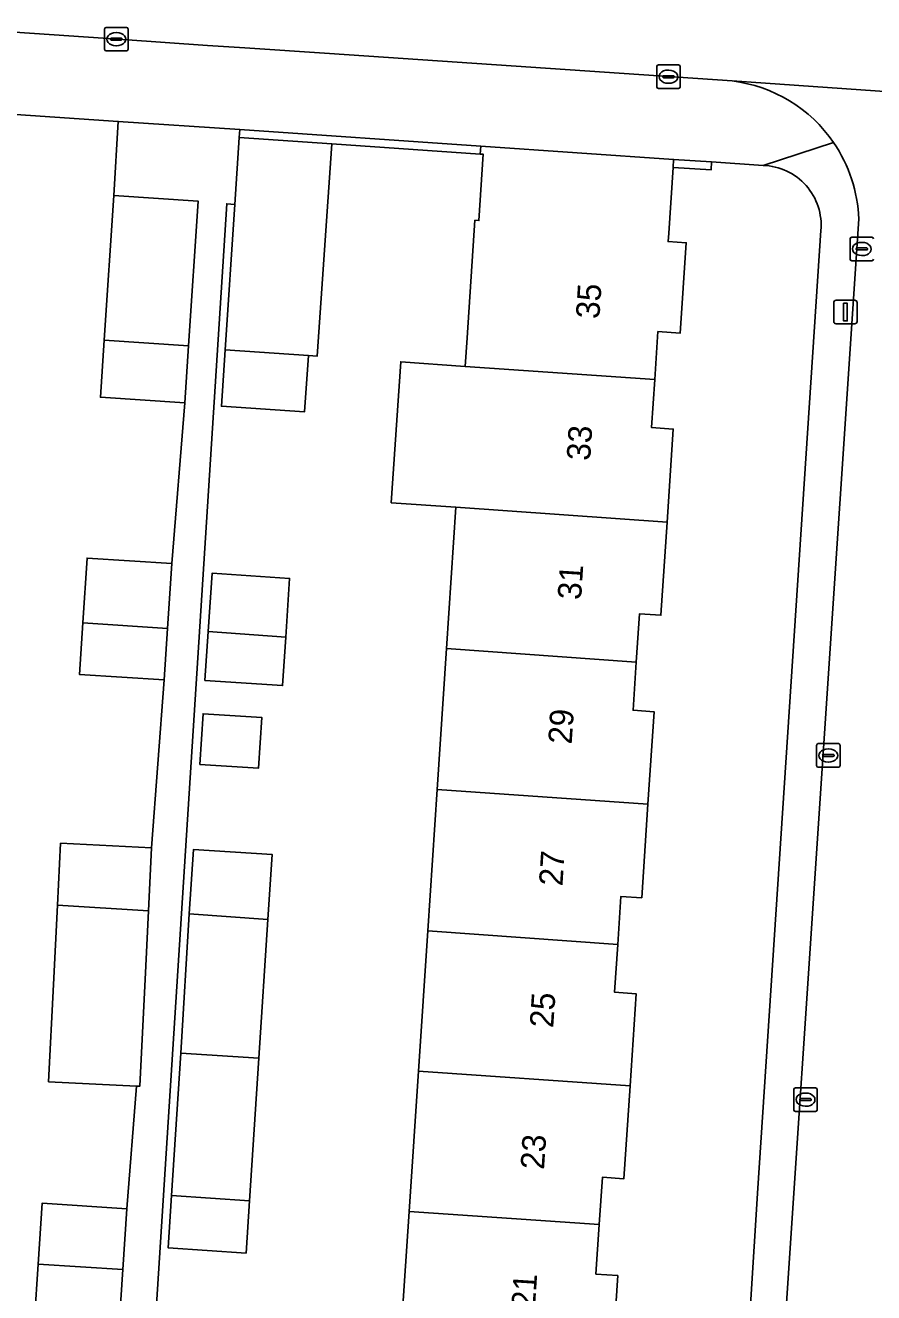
# Model space of a CAD drawing. Extents: x 161848 to 162726, y 385382 to 386521.
# Drawn here: x 162343.6 to 162379.6, y 385539 to 385592.8 of the extents above; entities that cross this region are included whole.
import ezdxf

# ---------------------------------------------------------------- set-up
doc = ezdxf.new("R2010")
doc.units = 0
for name, color, linetype in [('IMGEO_Erf', 7, 'Continuous'), ('IMGEO_Kolk', 7, 'Continuous'), ('IMGEO_Lichtmast', 7, 'Continuous'), ('IMGEO_Muur', 7, 'Continuous'), ('IMGEO_Pand', 7, 'Continuous'), ('IMGEO_Pand_nummerreeks', 7, 'Continuous'), ('IMGEO_Rijbaan_lokaal_open', 7, 'Continuous'), ('IMGEO_Voetpad_open', 7, 'Continuous')]:
    doc.layers.add(name, color=color, linetype=linetype)

msp = doc.modelspace()

# ---------------------------------------------------------------- linework, layer by layer
at = {"layer": 'IMGEO_Erf'}
for points in [[(162344.931, 385555.437), (162345.064, 385558.071), (162348.925, 385557.878), (162349.452, 385564.997), (162345.859, 385565.234), (162346.003, 385567.417), (162346.185, 385570.171), (162349.778, 385569.934), (162350.332, 385576.757), (162346.75, 385576.995), (162346.911, 385579.421), (162347.318, 385585.552), (162347.507, 385588.704), (162328.69, 385589.98)], [(162359.443, 385536.343), (162359.848, 385542.438), (162360.244, 385548.401), (162360.639, 385554.349), (162361.038, 385560.356), (162361.435, 385566.332), (162361.833, 385572.328), (162359.092, 385572.52), (162359.489, 385578.499), (162362.23, 385578.305), (162362.311, 385579.517), (162362.642, 385584.506), (162362.806, 385584.495), (162362.993, 385587.307), (162362.863, 385587.316), (162356.572, 385587.749), (162355.952, 385578.742), (162355.573, 385578.768), (162355.414, 385576.377), (162351.884, 385576.612), (162352.043, 385579.013), (162352.453, 385585.182), (162352.108, 385585.211), (162348.075, 385521.867)], [(162374.863, 385586.831), (162372.682, 385586.981), (162372.66, 385586.642), (162371.043, 385586.749), (162370.858, 385583.96), (162370.834, 385583.603), (162371.603, 385583.552), (162371.348, 385579.722), (162370.404, 385579.785), (162370.268, 385577.746), (162370.133, 385575.709), (162371.053, 385575.648), (162370.791, 385571.701), (162370.528, 385567.747), (162369.621, 385567.808), (162369.485, 385565.756), (162369.349, 385563.712), (162370.241, 385563.652), (162369.98, 385559.727), (162369.716, 385555.752), (162368.834, 385555.81), (162368.698, 385553.776), (162368.563, 385551.742), (162369.479, 385551.681), (162369.22, 385547.775), (162368.958, 385543.829), (162368.044, 385543.89), (162367.911, 385541.894), (162367.771, 385539.781), (162368.697, 385539.719), (162368.427, 385535.653)], [(162369.909, 385470.592), (162371.906, 385500), (162374.647, 385543.436), (162377.315, 385584.068)], [(162343.956, 385537.86), (162344.111, 385540.203), (162344.282, 385542.797), (162347.875, 385542.56), (162348.278, 385547.759), (162344.554, 385547.946), (162344.762, 385552.078), (162344.931, 385555.437)]]:
    msp.add_lwpolyline(points, dxfattribs=at)
for points in [[(162351.188, 385564.975), (162351.325, 385567.055), (162351.488, 385569.526), (162354.777, 385569.309), (162354.613, 385566.82), (162354.477, 385564.757)], [(162350.966, 385561.409), (162351.104, 385563.567), (162353.595, 385563.407), (162353.457, 385561.249)], [(162349.626, 385540.892), (162349.773, 385543.118), (162350.17, 385549.166), (162350.523, 385555.068), (162350.703, 385557.807), (162354.042, 385557.586), (162353.86, 385554.831), (162353.471, 385548.948), (162353.079, 385542.894), (162352.933, 385540.674)]]:
    msp.add_lwpolyline(points, close=True, dxfattribs=at)
msp.add_arc((162374.795, 385584.301), 2.531, 354.7185, 88.4558, dxfattribs=at)
at = {"layer": 'IMGEO_Kolk'}
for p, q in [((162346.926, 385591.766), (162346.926, 385592.618)), ((162347.001, 385592.692), (162347.853, 385592.692)), ((162347.927, 385592.618), (162347.927, 385591.766)), ((162347.185, 385592.186), (162347.185, 385592.198)), ((162347.623, 385592.149), (162347.225, 385592.149)), ((162347.228, 385592.235), (162347.626, 385592.235)), ((162347.414, 385592.472), (162347.439, 385592.472)), ((162347.669, 385592.198), (162347.669, 385592.186)), ((162347.853, 385591.692), (162347.001, 385591.692)), ((162347.437, 385591.912), (162347.412, 385591.912)), ((162370.35, 385590.174), (162370.35, 385591.026)), ((162370.425, 385591.1), (162371.277, 385591.1)), ((162371.351, 385591.026), (162371.351, 385590.174)), ((162370.609, 385590.594), (162370.609, 385590.606)), ((162371.047, 385590.557), (162370.649, 385590.557)), ((162370.652, 385590.643), (162371.05, 385590.643)), ((162370.838, 385590.88), (162370.863, 385590.88)), ((162371.093, 385590.606), (162371.093, 385590.594)), ((162371.277, 385590.1), (162370.425, 385590.1)), ((162370.861, 385590.32), (162370.836, 385590.32)), ((162378.552, 385582.862), (162378.552, 385583.714)), ((162378.627, 385583.788), (162379.479, 385583.788)), ((162379.04, 385583.568), (162379.065, 385583.568)), ((162378.811, 385583.282), (162378.811, 385583.294)), ((162379.249, 385583.245), (162378.851, 385583.245)), ((162378.854, 385583.331), (162379.252, 385583.331)), ((162379.063, 385583.008), (162379.038, 385583.008)), ((162379.295, 385583.294), (162379.295, 385583.282)), ((162379.479, 385582.788), (162378.627, 385582.788)), ((162377.132, 385561.369), (162377.132, 385562.221)), ((162377.207, 385562.295), (162378.059, 385562.295)), ((162377.62, 385562.075), (162377.645, 385562.075)), ((162378.133, 385562.221), (162378.133, 385561.369)), ((162377.391, 385561.789), (162377.391, 385561.801)), ((162377.829, 385561.752), (162377.431, 385561.752)), ((162377.434, 385561.838), (162377.832, 385561.838)), ((162377.643, 385561.515), (162377.618, 385561.515)), ((162377.875, 385561.801), (162377.875, 385561.789)), ((162378.059, 385561.295), (162377.207, 385561.295)), ((162376.163, 385546.761), (162376.163, 385547.613)), ((162376.238, 385547.687), (162377.09, 385547.687)), ((162376.651, 385547.467), (162376.676, 385547.467)), ((162377.164, 385547.613), (162377.164, 385546.761)), ((162376.422, 385547.181), (162376.422, 385547.193)), ((162376.86, 385547.144), (162376.462, 385547.144)), ((162376.465, 385547.23), (162376.863, 385547.23)), ((162376.674, 385546.907), (162376.649, 385546.907)), ((162376.906, 385547.193), (162376.906, 385547.181)), ((162377.09, 385546.687), (162376.238, 385546.687))]:
    msp.add_line(p, q, dxfattribs=at)
for points in [[(162346.926, 385591.766), (162346.926, 385592.618)], [(162347.001, 385592.692), (162347.853, 385592.692)], [(162347.927, 385592.618), (162347.927, 385591.766)], [(162347.853, 385591.692), (162347.001, 385591.692)], [(162370.35, 385590.174), (162370.35, 385591.026)], [(162370.425, 385591.1), (162371.277, 385591.1)], [(162371.351, 385591.026), (162371.351, 385590.174)], [(162371.277, 385590.1), (162370.425, 385590.1)], [(162378.552, 385582.862), (162378.552, 385583.714)], [(162378.627, 385583.788), (162379.479, 385583.788)], [(162379.479, 385582.788), (162378.627, 385582.788)], [(162377.132, 385561.369), (162377.132, 385562.221)], [(162377.207, 385562.295), (162378.059, 385562.295)], [(162378.133, 385562.221), (162378.133, 385561.369)], [(162378.059, 385561.295), (162377.207, 385561.295)], [(162376.163, 385546.761), (162376.163, 385547.613)], [(162376.238, 385547.687), (162377.09, 385547.687)], [(162377.164, 385547.613), (162377.164, 385546.761)], [(162377.09, 385546.687), (162376.238, 385546.687)]]:
    msp.add_lwpolyline(points, dxfattribs=at)
for centre, radius, start, end in [((162347.003, 385592.616), 0.0765, 91.552, 178.448), ((162347.003, 385592.616), 0.0765, 91.552, 178.448), ((162347.851, 385592.616), 0.0765, 1.552, 88.448), ((162347.851, 385592.616), 0.0765, 1.552, 88.448), ((162347.225, 385592.195), 0.0403, 85.8775, 175.7526), ((162347.222, 385592.185), 0.0366, 178.938, 274.7102), ((162347.626, 385592.192), 0.043, 264.8664, 352.4533), ((162347.63, 385592.197), 0.0386, 1.7309, 96.639), ((162347.003, 385591.768), 0.0765, 181.552, 268.448), ((162347.003, 385591.768), 0.0765, 181.552, 268.448), ((162347.851, 385591.768), 0.0765, 271.552, 358.448), ((162347.851, 385591.768), 0.0765, 271.552, 358.448), ((162370.427, 385591.024), 0.0765, 91.552, 178.448), ((162370.427, 385591.024), 0.0765, 91.552, 178.448), ((162371.275, 385591.024), 0.0765, 1.552, 88.448), ((162371.275, 385591.024), 0.0765, 1.552, 88.448), ((162370.649, 385590.603), 0.0403, 85.8775, 175.7526), ((162370.646, 385590.593), 0.0366, 178.938, 274.7102), ((162371.05, 385590.6), 0.043, 264.8664, 352.4533), ((162371.054, 385590.605), 0.0386, 1.7309, 96.639), ((162370.427, 385590.176), 0.0765, 181.552, 268.448), ((162370.427, 385590.176), 0.0765, 181.552, 268.448), ((162371.275, 385590.176), 0.0765, 271.552, 358.448), ((162371.275, 385590.176), 0.0765, 271.552, 358.448), ((162378.629, 385583.712), 0.0765, 91.552, 178.448), ((162378.629, 385583.712), 0.0765, 91.552, 178.448), ((162379.477, 385583.712), 0.0765, 1.552, 88.448), ((162379.477, 385583.712), 0.0765, 1.552, 88.448), ((162378.851, 385583.291), 0.0403, 85.8775, 175.7526), ((162378.848, 385583.281), 0.0366, 178.938, 274.7102), ((162379.252, 385583.288), 0.043, 264.8664, 352.4533), ((162379.256, 385583.293), 0.0386, 1.7309, 96.639), ((162378.629, 385582.864), 0.0765, 181.552, 268.448), ((162378.629, 385582.864), 0.0765, 181.552, 268.448), ((162379.477, 385582.864), 0.0765, 271.552, 358.448), ((162379.477, 385582.864), 0.0765, 271.552, 358.448), ((162377.209, 385562.219), 0.0765, 91.552, 178.448), ((162377.209, 385562.219), 0.0765, 91.552, 178.448), ((162378.057, 385562.219), 0.0765, 1.552, 88.448), ((162378.057, 385562.219), 0.0765, 1.552, 88.448), ((162377.431, 385561.798), 0.0403, 85.8775, 175.7526), ((162377.428, 385561.788), 0.0366, 178.938, 274.7102), ((162377.832, 385561.795), 0.043, 264.8664, 352.4533), ((162377.836, 385561.8), 0.0386, 1.7309, 96.639), ((162377.209, 385561.371), 0.0765, 181.552, 268.448), ((162377.209, 385561.371), 0.0765, 181.552, 268.448), ((162378.057, 385561.371), 0.0765, 271.552, 358.448), ((162378.057, 385561.371), 0.0765, 271.552, 358.448), ((162376.24, 385547.611), 0.0765, 91.552, 178.448), ((162376.24, 385547.611), 0.0765, 91.552, 178.448), ((162377.088, 385547.611), 0.0765, 1.552, 88.448), ((162377.088, 385547.611), 0.0765, 1.552, 88.448), ((162376.462, 385547.19), 0.0403, 85.8775, 175.7526), ((162376.459, 385547.18), 0.0366, 178.938, 274.7102), ((162376.863, 385547.187), 0.043, 264.8664, 352.4533), ((162376.867, 385547.192), 0.0386, 1.7309, 96.639), ((162376.24, 385546.763), 0.0765, 181.552, 268.448), ((162376.24, 385546.763), 0.0765, 181.552, 268.448), ((162377.088, 385546.763), 0.0765, 271.552, 358.448), ((162377.088, 385546.763), 0.0765, 271.552, 358.448)]:
    msp.add_arc(centre, radius, start, end, dxfattribs=at)
for centre, major_axis, ratio, start_param, end_param in [((162347.413, 385592.192), (-0.387, 0.002), 0.722429, 4.712389, 7.853982), ((162347.438, 385592.192), (-0.39, 0.002), 0.717154, 1.570796, 4.712389), ((162370.837, 385590.6), (-0.387, 0.002), 0.722429, 4.712389, 7.853982), ((162370.862, 385590.6), (-0.39, 0.002), 0.717154, 1.570796, 4.712389), ((162379.039, 385583.288), (-0.387, 0.002), 0.722429, 4.712389, 7.853982), ((162379.064, 385583.288), (-0.39, 0.002), 0.717154, 1.570796, 4.712389), ((162377.619, 385561.795), (-0.387, 0.002), 0.722429, 4.712389, 7.853982), ((162377.644, 385561.795), (-0.39, 0.002), 0.717154, 1.570796, 4.712389), ((162376.65, 385547.187), (-0.387, 0.002), 0.722429, 4.712389, 7.853982), ((162376.675, 385547.187), (-0.39, 0.002), 0.717154, 1.570796, 4.712389)]:
    msp.add_ellipse(centre, major_axis=major_axis, ratio=ratio, start_param=start_param, end_param=end_param, dxfattribs=at)
at = {"layer": 'IMGEO_Lichtmast'}
for p, q in [((162377.861, 385580.211), (162377.861, 385581.011)), ((162377.861, 385581.011), (162377.861, 385580.211)), ((162377.961, 385581.111), (162378.751, 385581.111)), ((162378.751, 385581.111), (162377.961, 385581.111)), ((162378.851, 385581.011), (162378.851, 385580.211)), ((162378.851, 385580.211), (162378.851, 385581.011)), ((162378.751, 385580.111), (162377.961, 385580.111)), ((162377.961, 385580.111), (162378.751, 385580.111))]:
    msp.add_line(p, q, dxfattribs=at)
msp.add_lwpolyline([(162378.281, 385580.986), (162378.431, 385580.986), (162378.431, 385580.236), (162378.281, 385580.236), (162378.281, 385580.986)], dxfattribs=at)
for centre, start, end in [((162377.961, 385581.011), 90, 180), ((162377.961, 385581.011), 90, 180), ((162378.751, 385581.011), 0, 90), ((162378.751, 385581.011), 360, 90), ((162377.961, 385580.211), 180, 270), ((162377.961, 385580.211), 180, 270), ((162378.751, 385580.211), 270, 0), ((162378.751, 385580.211), 270, 0)]:
    msp.add_arc(centre, 0.1, start, end, dxfattribs=at)
at = {"layer": 'IMGEO_Muur'}
for points in [[(162352.664, 385588.358), (162352.641, 385588.019), (162356.572, 385587.749), (162362.863, 385587.316), (162362.885, 385587.655)], [(162371.066, 385587.092), (162371.043, 385586.749), (162372.66, 385586.642), (162372.682, 385586.981)]]:
    msp.add_lwpolyline(points, close=True, dxfattribs=at)
msp.add_lwpolyline([(162352.453, 385585.182), (162352.641, 385588.019)], dxfattribs=at)
at = {"layer": 'IMGEO_Pand'}
for points in [[(162356.572, 385587.749), (162352.641, 385588.019), (162352.453, 385585.182), (162352.043, 385579.013), (162355.573, 385578.768), (162355.952, 385578.742)], [(162362.885, 385587.655), (162362.863, 385587.316), (162362.993, 385587.307), (162362.806, 385584.495), (162362.642, 385584.506), (162362.311, 385579.517), (162362.23, 385578.305), (162370.268, 385577.746), (162370.404, 385579.785), (162371.348, 385579.722), (162371.603, 385583.552), (162370.834, 385583.603), (162370.858, 385583.96), (162371.043, 385586.749), (162371.066, 385587.092)], [(162347.318, 385585.552), (162346.911, 385579.421), (162350.493, 385579.181), (162350.9, 385585.314)], [(162346.911, 385579.421), (162346.75, 385576.995), (162350.332, 385576.757), (162350.493, 385579.181)], [(162352.043, 385579.013), (162351.884, 385576.612), (162355.414, 385576.377), (162355.573, 385578.768)], [(162370.791, 385571.701), (162371.053, 385575.648), (162370.133, 385575.709), (162370.268, 385577.746), (162362.23, 385578.305), (162359.489, 385578.499), (162359.092, 385572.52), (162361.833, 385572.328)], [(162369.485, 385565.756), (162369.621, 385567.808), (162370.528, 385567.747), (162370.791, 385571.701), (162361.833, 385572.328), (162361.435, 385566.332)], [(162346.003, 385567.417), (162349.596, 385567.18), (162349.778, 385569.934), (162346.185, 385570.171)], [(162351.325, 385567.055), (162354.613, 385566.82), (162354.777, 385569.309), (162351.488, 385569.526)], [(162349.596, 385567.18), (162346.003, 385567.417), (162345.859, 385565.234), (162349.452, 385564.997)], [(162354.613, 385566.82), (162351.325, 385567.055), (162351.188, 385564.975), (162354.477, 385564.757)], [(162369.98, 385559.727), (162370.241, 385563.652), (162369.349, 385563.712), (162369.485, 385565.756), (162361.435, 385566.332), (162361.038, 385560.356)], [(162350.966, 385561.409), (162353.457, 385561.249), (162353.595, 385563.407), (162351.104, 385563.567)], [(162361.038, 385560.356), (162360.639, 385554.349), (162368.698, 385553.776), (162368.834, 385555.81), (162369.716, 385555.752), (162369.98, 385559.727)], [(162348.925, 385557.878), (162345.064, 385558.071), (162344.931, 385555.437), (162348.791, 385555.194)], [(162350.523, 385555.068), (162353.86, 385554.831), (162354.042, 385557.586), (162350.703, 385557.807)], [(162348.791, 385555.194), (162344.931, 385555.437), (162344.762, 385552.078), (162344.554, 385547.946), (162348.278, 385547.759), (162348.417, 385547.752), (162348.674, 385552.867)], [(162353.86, 385554.831), (162350.523, 385555.068), (162350.17, 385549.166), (162353.471, 385548.948)], [(162369.22, 385547.775), (162369.479, 385551.681), (162368.563, 385551.742), (162368.698, 385553.776), (162360.639, 385554.349), (162360.244, 385548.401)], [(162353.471, 385548.948), (162350.17, 385549.166), (162349.773, 385543.118), (162353.079, 385542.894)], [(162367.911, 385541.894), (162368.044, 385543.89), (162368.958, 385543.829), (162369.22, 385547.775), (162360.244, 385548.401), (162359.848, 385542.438)], [(162347.705, 385539.985), (162347.875, 385542.56), (162344.282, 385542.797), (162344.111, 385540.203)], [(162353.079, 385542.894), (162349.773, 385543.118), (162349.626, 385540.892), (162352.933, 385540.674)], [(162359.848, 385542.438), (162359.443, 385536.343), (162368.427, 385535.653), (162368.697, 385539.719), (162367.771, 385539.781), (162367.911, 385541.894)], [(162347.705, 385539.985), (162344.111, 385540.203), (162343.956, 385537.86), (162344.976, 385537.793), (162347.549, 385537.623)]]:
    msp.add_lwpolyline(points, close=True, dxfattribs=at)
at = {"layer": 'IMGEO_Rijbaan_lokaal_open'}
for points in [[(162328.746, 385593.462), (162347.698, 385592.175), (162351.299, 385591.93), (162352.879, 385591.823), (162356.465, 385591.579), (162373.555, 385590.418), (162391.947, 385589.134)], [(162391.947, 385589.134), (162373.555, 385590.418)], [(162378.92, 385584.563), (162374.078, 385511.821), (162373.801, 385507.691), (162372.417, 385487.277), (162371.337, 385471.56)]]:
    msp.add_lwpolyline(points, dxfattribs=at)
for centre, radius, start, end in [((162372.814, 385584.352), 6.111, 34.3801, 83.0327), ((162372.814, 385584.354), 6.11, 1.9604, 34.3675)]:
    msp.add_arc(centre, radius, start, end, dxfattribs=at)
at = {"layer": 'IMGEO_Voetpad_open'}
for points in [[(162373.555, 385590.418), (162356.465, 385591.579), (162352.879, 385591.823), (162351.299, 385591.93), (162347.698, 385592.175), (162328.746, 385593.462)], [(162328.69, 385589.98), (162347.507, 385588.704), (162352.664, 385588.358), (162362.885, 385587.655), (162371.066, 385587.092), (162372.682, 385586.981), (162374.863, 385586.831), (162377.857, 385587.803)], [(162348.075, 385521.867), (162352.108, 385585.211), (162352.453, 385585.182), (162352.641, 385588.019), (162352.664, 385588.358), (162347.507, 385588.704), (162347.318, 385585.552), (162350.9, 385585.314), (162350.493, 385579.181), (162350.332, 385576.757), (162349.778, 385569.934), (162349.596, 385567.18), (162349.452, 385564.997), (162348.925, 385557.878), (162348.791, 385555.194), (162348.674, 385552.867), (162348.417, 385547.752), (162348.278, 385547.759), (162347.875, 385542.56), (162347.705, 385539.985), (162347.549, 385537.623)], [(162377.857, 385587.803), (162374.863, 385586.831)], [(162371.337, 385471.56), (162372.417, 385487.277), (162373.801, 385507.691), (162374.078, 385511.821), (162378.92, 385584.563)], [(162377.315, 385584.068), (162374.647, 385543.436), (162371.906, 385500), (162369.909, 385470.592)]]:
    msp.add_lwpolyline(points, dxfattribs=at)
for centre, radius, start, end in [((162372.814, 385584.352), 6.111, 34.3801, 83.0327), ((162372.814, 385584.354), 6.11, 1.9604, 34.3675), ((162374.795, 385584.301), 2.531, 354.7185, 88.4558)]:
    msp.add_arc(centre, radius, start, end, dxfattribs=at)

# ---------------------------------------------------------------- texts
at = {"layer": 'IMGEO_Pand_nummerreeks'}
for s, p in [('35', (162367.915, 385580.302)), ('33', (162367.524, 385574.285)), ('31', (162367.14, 385568.38)), ('29', (162366.742, 385562.25)), ('27', (162366.351, 385556.232)), ('25', (162365.96, 385550.215)), ('23', (162365.569, 385544.197)), ('21', (162365.185, 385538.293))]:
    msp.add_text(s, height=1, rotation=86.282, dxfattribs=at).set_placement(p)

doc.saveas('drawing.dxf')
